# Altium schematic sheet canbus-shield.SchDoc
size A
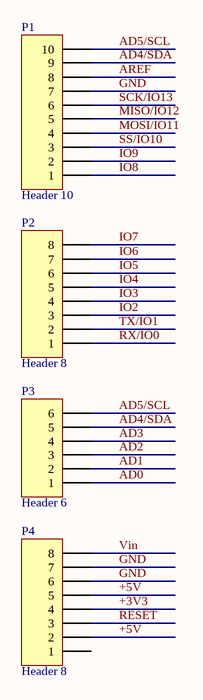
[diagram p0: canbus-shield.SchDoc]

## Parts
P1  Header 10  [HDR1X10]
P2  Header 8  [HDR1X8]
P3  Header 6  [HDR1X6]
P4  Header 8  [HDR1X8]

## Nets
+3V3: P4.4
+5V: P4.2 P4.5
AD0: P3.1
AD1: P3.2
AD2: P3.3
AD3: P3.4
AD4/SDA: P1.9 P3.5
AD5/SCL: P1.10 P3.6
AREF: P1.8
GND: P1.7 P4.6 P4.7
IO2: P2.3
IO3: P2.4
IO4: P2.5
IO5: P2.6
IO6: P2.7
IO7: P2.8
IO8: P1.1
IO9: P1.2
MISO/IO12: P1.5
MOSI/IO11: P1.4
RESET: P4.3
RX/IO0: P2.1
SCK/IO13: P1.6
SS/IO10: P1.3
TX/IO1: P2.2
Vin: P4.8

Not connected (* = marked no-connect by the designer): P4 1

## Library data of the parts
P1 = Header 10: Header, 10-Pin
P2 P4 = Header 8: Header, 8-Pin
P3 = Header 6: Header, 6-Pin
